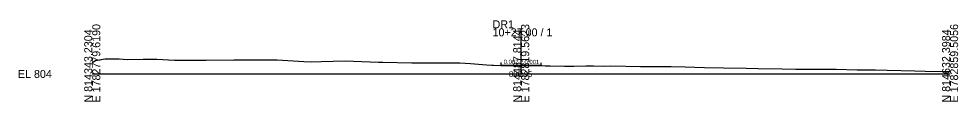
# Model space of a CAD drawing. Extents: x -26 to 303, y -10 to 2017.
# Drawn here: x -25.7 to 302.8, y 490.3 to 518.8 of the extents above; entities that cross this region are included whole.
import ezdxf

# ---------------------------------------------------------------- set-up
doc = ezdxf.new("R2010")
doc.units = 0
for name, color, linetype in [('Exist Cross Section Cell', 7, 'Continuous'), ('Exist XS Center Line Elevation Label', 7, 'Continuous'), ('Exist XS Ground Line', 7, 'Continuous'), ('Prop XS Dump Level', 7, 'Continuous'), ('Prop XS EOT Tick Mark', 7, 'Continuous'), ('Prop XS Finish Grade Pavement', 7, 'Continuous'), ('Prop XS SE Text', 7, 'Continuous')]:
    doc.layers.add(name, color=color, linetype=linetype)

msp = doc.modelspace()

# ---------------------------------------------------------------- linework, layer by layer
at = {"layer": 'Exist Cross Section Cell'}
for p, q in [((150, 500), (150, 515.96)), ((0, 500), (150, 500)), ((150, 500), (300, 500))]:
    msp.add_line(p, q, dxfattribs=at)
at = {"layer": 'Exist XS Ground Line'}
for p, q in [((0, 503.97), (1.09, 504.76)), ((1.09, 504.76), (4.49, 505.29)), ((4.49, 505.29), (5.46, 505.31)), ((5.46, 505.31), (9.41, 505.32)), ((9.41, 505.32), (12.26, 505.1)), ((12.26, 505.1), (17.75, 505.21)), ((17.75, 505.21), (22.56, 505.17)), ((22.56, 505.17), (28.77, 504.8)), ((28.77, 504.8), (39.84, 504.8)), ((39.84, 504.8), (49.5, 504.95)), ((49.5, 504.95), (64.65, 504.89)), ((64.65, 504.89), (74.04, 504.35)), ((74.04, 504.35), (76.62, 504.29)), ((76.62, 504.29), (80.1, 504.32)), ((80.1, 504.32), (88.41, 504.65)), ((88.41, 504.65), (97.15, 504.25)), ((97.15, 504.25), (100.06, 504.11)), ((100.06, 504.11), (100.53, 504.11)), ((100.53, 504.11), (101.66, 504.08)), ((101.66, 504.08), (111.82, 503.86)), ((111.82, 503.86), (113.84, 503.85)), ((113.84, 503.85), (120.08, 503.91)), ((120.08, 503.91), (126.38, 503.9)), ((126.38, 503.9), (128.57, 503.84)), ((128.57, 503.84), (132.23, 503.61)), ((132.23, 503.61), (135.11, 503.41)), ((135.11, 503.41), (137.93, 503.22)), ((137.93, 503.22), (139.74, 503.08)), ((139.74, 503.08), (140.31, 503.06)), ((140.31, 503.06), (142.88, 502.98)), ((142.88, 502.98), (145.14, 502.99)), ((145.14, 502.99), (150, 502.95)), ((150, 502.95), (155.19, 502.95)), ((155.19, 502.95), (157.32, 502.95)), ((157.32, 502.95), (158.4, 502.9)), ((158.4, 502.9), (160.18, 502.84)), ((160.18, 502.84), (165.11, 502.67)), ((165.11, 502.67), (168.36, 502.77)), ((168.36, 502.77), (172.67, 502.79)), ((172.67, 502.79), (175.24, 502.8)), ((175.24, 502.8), (178.91, 502.77)), ((178.91, 502.77), (181.36, 502.79)), ((181.36, 502.79), (191.71, 502.64)), ((191.71, 502.64), (195.04, 502.6)), ((195.04, 502.6), (202.42, 502.56)), ((202.42, 502.56), (207.33, 502.5)), ((207.33, 502.5), (214.07, 502.21)), ((214.07, 502.21), (220.78, 502.09)), ((220.78, 502.09), (228.72, 502.03)), ((228.72, 502.03), (232.86, 501.91)), ((232.86, 501.91), (241.23, 501.81)), ((241.23, 501.81), (246.09, 501.68)), ((246.09, 501.68), (256.49, 501.67)), ((256.49, 501.67), (260.15, 501.7)), ((260.15, 501.7), (267.54, 501.45)), ((267.54, 501.45), (273.87, 501.39)), ((273.87, 501.39), (277.99, 501.32)), ((277.99, 501.32), (287.68, 501.04)), ((287.68, 501.04), (291.24, 500.99)), ((291.24, 500.99), (300, 500.83))]:
    msp.add_line(p, q, dxfattribs=at)
at = {"layer": 'Prop XS Dump Level'}
for p, q in [((150, 502.95), (143, 503)), ((157, 502.95), (150, 502.95))]:
    msp.add_line(p, q, dxfattribs=at)
at = {"layer": 'Prop XS EOT Tick Mark'}
for p, q in [((143, 503), (143, 504)), ((157, 502.95), (157, 503.95))]:
    msp.add_line(p, q, dxfattribs=at)
at = {"layer": 'Prop XS Finish Grade Pavement'}
for p, q in [((143, 503), (150, 502.95)), ((150, 502.95), (157, 502.95))]:
    msp.add_line(p, q, dxfattribs=at)

# ---------------------------------------------------------------- texts
at = {"layer": 'Exist Cross Section Cell'}
for s, p in [('E 1782779.6190', (2.8, 490)), ('E 1782819.5623', (152.8, 490)), ('E 1782859.5056', (302.8, 490)), ('N 814343.2304', (0, 490)), ('N 814487.8144', (150, 490)), ('N 814632.3984', (300, 490))]:
    msp.add_text(s, height=2.8, rotation=90, dxfattribs=at).set_placement(p)
for s, p in [('10+27.00 / 1', (140, 513.16)), ('DR1', (140, 515.96)), ('EL 804', (-26, 498.6))]:
    msp.add_text(s, height=2.8, dxfattribs=at).set_placement(p)
at = {"layer": 'Exist XS Center Line Elevation Label'}
msp.add_text('806.95', height=2, dxfattribs=at).set_placement((145.74, 498.95))
at = {"layer": 'Prop XS SE Text'}
for s, rotation, p in [('0.007', 359.576, (143.87, 503.5)), ('0.001', 359.9427, (151.15, 503.45))]:
    msp.add_text(s, height=1.5, rotation=rotation, dxfattribs=at).set_placement(p)

doc.saveas('drawing.dxf')
